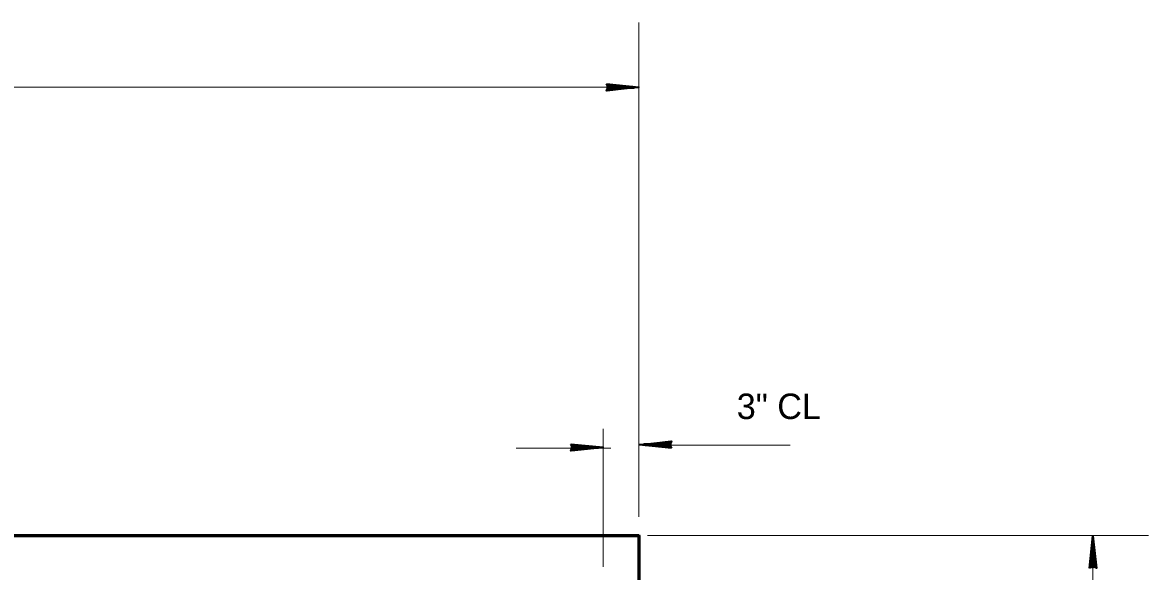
# Model space of a CAD drawing. Extents: x 6.34 to 9.53, y -1.46 to 0.53.
# Drawn here: x 7.1006 to 7.4689, y -0.4014 to -0.2218 of the extents above; entities that cross this region are included whole.
import ezdxf

# ---------------------------------------------------------------- set-up
doc = ezdxf.new("R2010")
doc.units = 0
doc.header["$LTSCALE"] = 0.0033
doc.layers.add('1', color=7, linetype='Continuous', lineweight=40)

msp = doc.modelspace()

# ---------------------------------------------------------------- linework, layer by layer
at = {"layer": '1', "lineweight": 13}
for p, q in [((7.30225, -0.3835), (7.30225, -0.22175)), ((7.290583, -0.399833), (7.290583, -0.35475)), ((7.30225, -0.35625), (7.30225, -0.355917)), ((7.30225, -0.35625), (7.302333, -0.35625)), ((7.312917, -0.360083), (7.351667, -0.360083)), ((7.262083, -0.361), (7.293, -0.361)), ((7.305083, -0.389583), (7.468917, -0.389583)), ((7.45075, -0.391417), (7.45075, -0.80625))]:
    msp.add_line(p, q, dxfattribs=at)
at = {"layer": '1', "lineweight": 35}
for p, q in [((7.291583, -0.242917), (7.302167, -0.242917)), ((7.29175, -0.243583), (7.299083, -0.242833)), ((7.291833, -0.241917), (7.299667, -0.242833)), ((7.291833, -0.241917), (7.299667, -0.242833)), ((7.291833, -0.242), (7.299667, -0.242833)), ((7.291833, -0.242083), (7.299667, -0.242917)), ((7.291833, -0.242083), (7.299667, -0.243083)), ((7.291833, -0.24375), (7.299167, -0.242917)), ((7.291833, -0.243833), (7.299167, -0.243083)), ((7.291833, -0.244), (7.299167, -0.243167)), ((7.279917, -0.36075), (7.2905, -0.36075)), ((7.280083, -0.361417), (7.287417, -0.360667)), ((7.280167, -0.35975), (7.288, -0.360667)), ((7.280167, -0.35975), (7.288, -0.360667)), ((7.280167, -0.359833), (7.288, -0.360667)), ((7.280167, -0.359917), (7.288, -0.36075)), ((7.280167, -0.359917), (7.288, -0.360917)), ((7.280167, -0.361583), (7.2875, -0.36075)), ((7.280167, -0.361667), (7.2875, -0.360917)), ((7.312917, -0.359917), (7.302333, -0.359917)), ((7.312667, -0.36075), (7.304833, -0.35975)), ((7.312667, -0.36075), (7.304833, -0.359917)), ((7.312667, -0.360917), (7.304833, -0.36)), ((7.312667, -0.360917), (7.304833, -0.36)), ((7.312667, -0.360833), (7.304833, -0.36)), ((7.312667, -0.358833), (7.305333, -0.359667)), ((7.312667, -0.359), (7.305333, -0.35975)), ((7.312667, -0.359083), (7.305333, -0.359917)), ((7.31275, -0.35925), (7.305417, -0.36)), ((7.280167, -0.361833), (7.2875, -0.361)), ((7.45075, -0.400333), (7.45075, -0.38975)), ((7.44975, -0.400083), (7.450667, -0.39225)), ((7.44975, -0.400083), (7.450667, -0.39225)), ((7.449833, -0.400083), (7.450667, -0.39225)), ((7.449917, -0.400083), (7.45075, -0.39225)), ((7.449917, -0.400083), (7.450917, -0.39225)), ((7.451417, -0.400167), (7.450667, -0.392833)), ((7.451583, -0.400083), (7.45075, -0.39275)), ((7.451667, -0.400083), (7.450917, -0.39275)), ((7.451833, -0.400083), (7.451, -0.39275))]:
    msp.add_line(p, q, dxfattribs=at)
at = {"layer": '1', "lineweight": 60}
for p, q in [((6.962167, -0.389583), (7.30225, -0.389583)), ((7.30225, -0.389583), (7.30225, -0.389417))]:
    msp.add_line(p, q, dxfattribs=at)
at = {"layer": '1', "lineweight": 13}
msp.add_lwpolyline([(6.71825, -0.242917), (7.021083, -0.242917), (7.301583, -0.242917)], dxfattribs=at)
at = {"layer": '1', "lineweight": 35}
for points in [[(7.291583, -0.241833), (7.302167, -0.242917), (7.291583, -0.244083), (7.292167, -0.242917)], [(7.292333, -0.242833), (7.297, -0.24275), (7.297, -0.242833), (7.296083, -0.242833), (7.292333, -0.24275), (7.295333, -0.242667), (7.292167, -0.242583), (7.294417, -0.2425), (7.292167, -0.242417), (7.295667, -0.242667), (7.300333, -0.242833), (7.299417, -0.243083), (7.300667, -0.243083), (7.292333, -0.243083), (7.29475, -0.24325), (7.292167, -0.24325), (7.2975, -0.242833), (7.292167, -0.2435)], [(7.279917, -0.359667), (7.2905, -0.36075), (7.279917, -0.361917), (7.2805, -0.36075)], [(7.280667, -0.360667), (7.285333, -0.360583), (7.285333, -0.360667), (7.284417, -0.360667), (7.280667, -0.360583), (7.283667, -0.3605), (7.2805, -0.360417), (7.28275, -0.360333), (7.2805, -0.36025), (7.284, -0.3605), (7.288667, -0.360667), (7.28775, -0.360917), (7.289, -0.360917), (7.280667, -0.360917), (7.283083, -0.361083), (7.2805, -0.361083), (7.285833, -0.360667), (7.2805, -0.361333)], [(7.312917, -0.361), (7.302333, -0.359917), (7.312917, -0.35875), (7.312333, -0.359917)], [(7.312167, -0.36), (7.3075, -0.360083), (7.3075, -0.36), (7.308417, -0.36), (7.312167, -0.360083), (7.309167, -0.360167), (7.312333, -0.36025), (7.310083, -0.360333), (7.312333, -0.360417), (7.308833, -0.360167), (7.304167, -0.36), (7.305083, -0.35975), (7.303833, -0.35975), (7.312167, -0.35975), (7.30975, -0.359583), (7.312333, -0.359583), (7.307, -0.36), (7.312333, -0.359333)], [(7.449667, -0.400333), (7.45075, -0.38975), (7.451917, -0.400333), (7.45075, -0.39975)], [(7.450667, -0.399583), (7.450583, -0.394917), (7.450667, -0.394917), (7.450667, -0.395833), (7.450583, -0.399583), (7.4505, -0.396583), (7.450417, -0.39975), (7.450333, -0.3975), (7.45025, -0.39975), (7.4505, -0.39625), (7.450667, -0.391583), (7.450917, -0.3925), (7.450917, -0.39125), (7.450917, -0.399583), (7.451083, -0.397167), (7.451083, -0.39975), (7.450667, -0.394417), (7.451333, -0.39975)]]:
    msp.add_lwpolyline(points, close=True, dxfattribs=at)
for points in [[(7.292333, -0.242833), (7.291917, -0.242083), (7.292167, -0.242333), (7.292333, -0.242667), (7.292583, -0.242583), (7.292417, -0.24225), (7.29225, -0.243), (7.292083, -0.2435), (7.291833, -0.243917)], [(7.280667, -0.360667), (7.28025, -0.359917), (7.2805, -0.360167), (7.280667, -0.3605), (7.280917, -0.360417), (7.28075, -0.360083), (7.280583, -0.360833), (7.280417, -0.361333), (7.280167, -0.36175)], [(7.312167, -0.36), (7.312583, -0.36075), (7.312333, -0.3605), (7.312167, -0.360167), (7.311917, -0.36025), (7.312083, -0.360583), (7.31225, -0.359833), (7.312417, -0.359333), (7.312667, -0.358917)], [(7.450667, -0.399583), (7.449917, -0.4), (7.450167, -0.39975), (7.4505, -0.399583), (7.450417, -0.399333), (7.450083, -0.3995), (7.450833, -0.399667), (7.451333, -0.399833), (7.45175, -0.400083)]]:
    msp.add_lwpolyline(points, dxfattribs=at)
at = {"layer": '1', "lineweight": 60}
msp.add_lwpolyline([(7.30225, -0.389583), (7.30225, -0.722917), (7.385583, -0.722917), (7.385583, -0.80625)], dxfattribs=at)

# ---------------------------------------------------------------- texts
at = {"layer": '1'}
msp.add_text('3" CL', height=0.008334, dxfattribs=at).set_placement((7.33425, -0.3515))

doc.saveas('drawing.dxf')
